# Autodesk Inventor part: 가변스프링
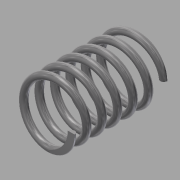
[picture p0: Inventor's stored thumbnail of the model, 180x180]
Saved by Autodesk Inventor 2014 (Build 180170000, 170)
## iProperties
Created: 2016-08
Part Number: 가변스프링
Material: 스테인레스 스틸
Document SubType Name: Modeling
Designer: SCD-A13
Density: 8.08 g/cm^3
Appearance: 반연마
Mass: 117.733 g
Surface Area: 118.259 cm^2
Volume: 14.571 cm^3
Author: SCD-A13
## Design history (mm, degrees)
sketch "스케치1"
  geometry: L1 (0, 0)-(20, 0); L2 (20, 0)-(20, 67.25); L3 (20, 67.25)-(0, 67.25); L4 (0, 67.25)-(0, 0); C1 r 2.5 at (20, 0)
  constraints: 8 end point, 2 parallel, 1 centre point, 1 coincident, 1 horizontal, 1 perpendicular
  dimensions: "d0" = 40 diameter of L1.end L4; "d1" = 67.25 distance of L3.end L1.start (derived); "d2" = 5 diameter of C1
feature "코일1" sketch "스케치1" pitch "d3" = 10; turns "d5" = 6; dims "d4" = 67.25 (= d1), "d6" = 0, angle "d7" = 90 deg, angle "d8" = 90 deg, "d9" = 0, "d10" = 0
node "작업 평면1"
sketch "스케치2"
  geometry: L1 (17.5, 0)-(22.5, 0) reference; 1 further point
  constraints: 1 horizontal alignment
extrude "돌출1" cut sketch "스케치2" stored distance "d12" = 10; taper "d13" = 0 deg
node "작업 평면2"
sketch "스케치3"
  geometry: L1 (-2.5, 0)-(2.5, 0) reference; 1 further point
  constraints: 1 horizontal alignment
extrude "돌출2" cut sketch "스케치3" stored distance "d15" = 10; taper "d16" = 0 deg
node "솔리드1"
node "절단 모서리 투영1"
node "절단 모서리 투영2"
other parameters: "d11" = 90 deg, "d14" = 90 deg
